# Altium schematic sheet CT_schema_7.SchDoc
size 556 x 419 mm
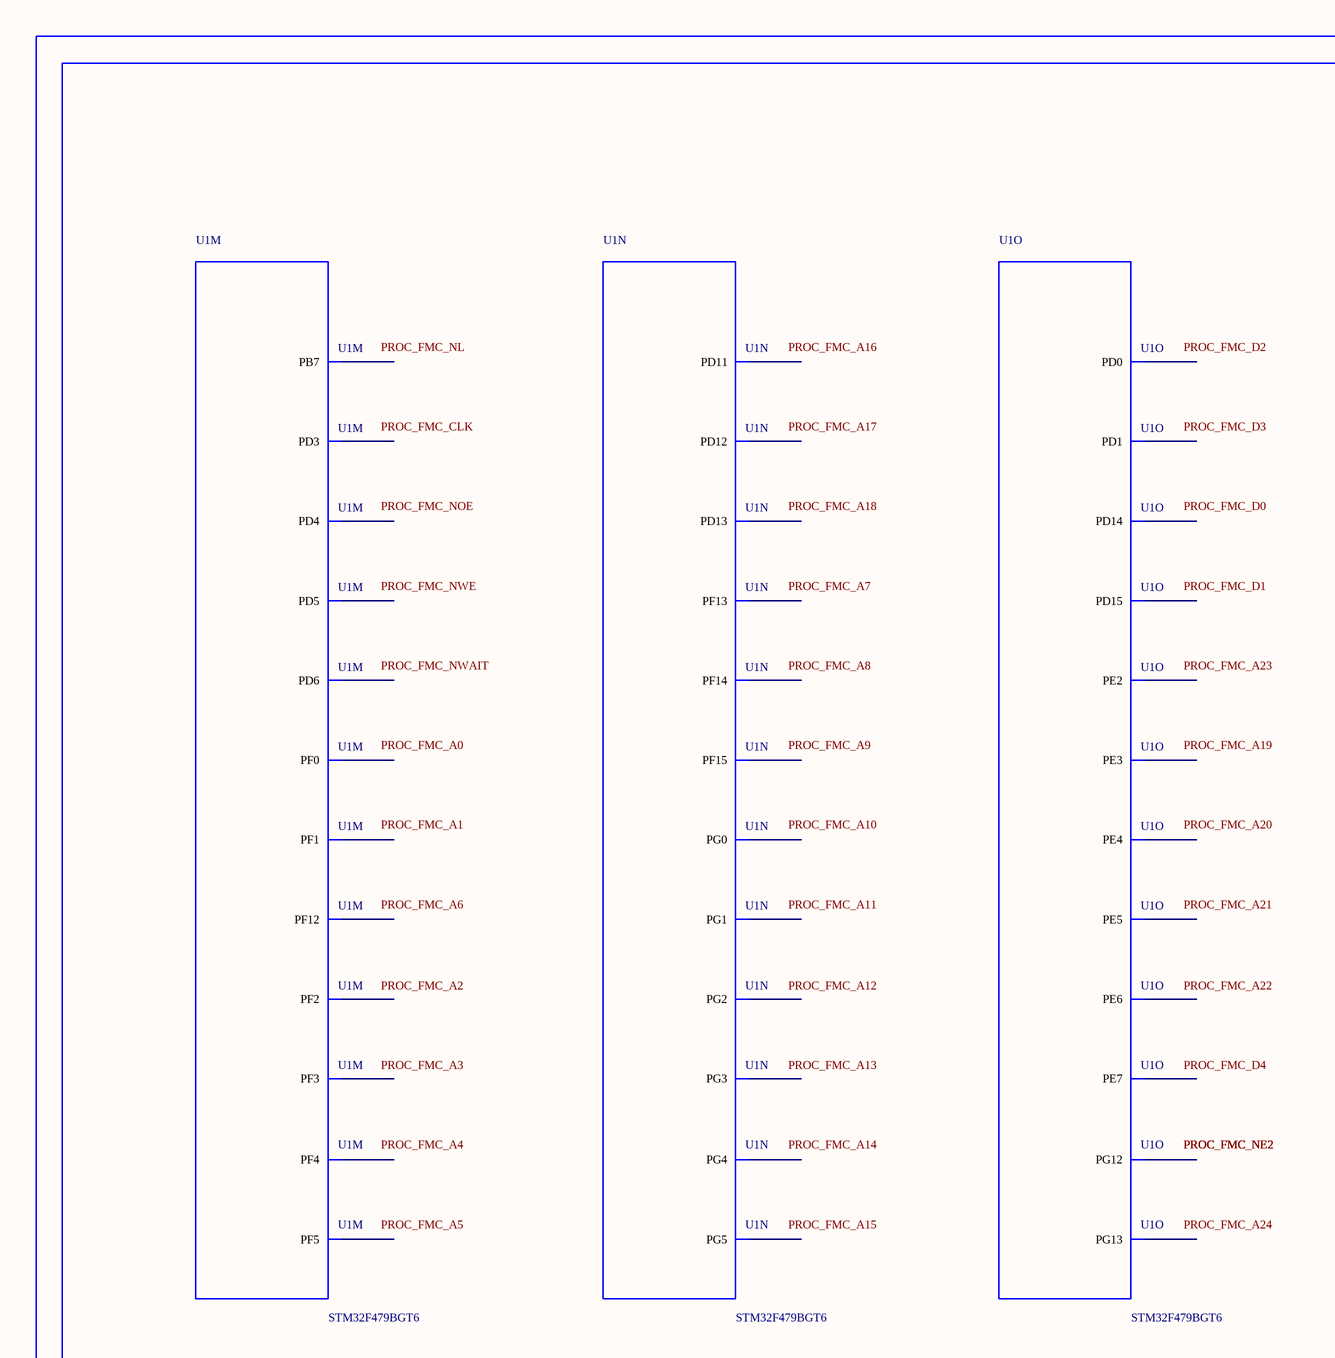
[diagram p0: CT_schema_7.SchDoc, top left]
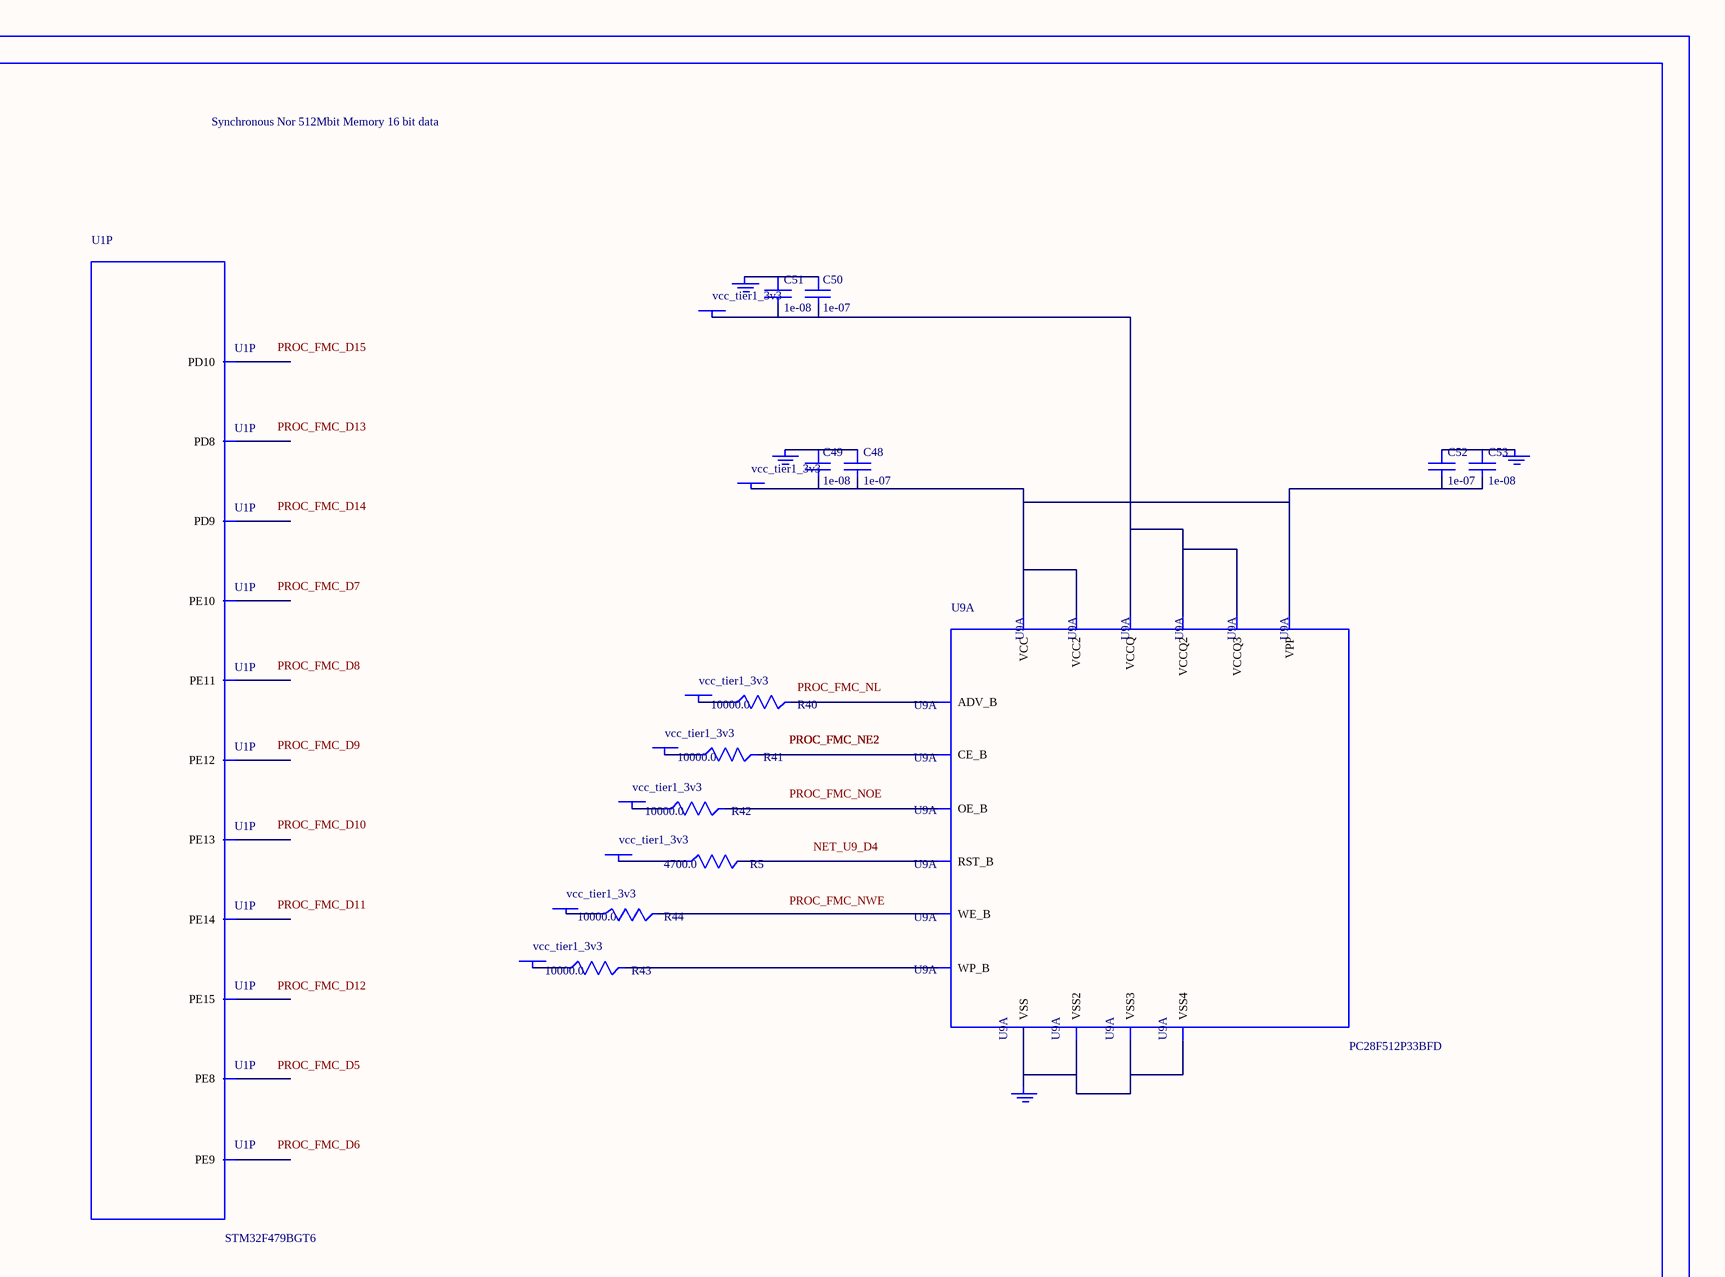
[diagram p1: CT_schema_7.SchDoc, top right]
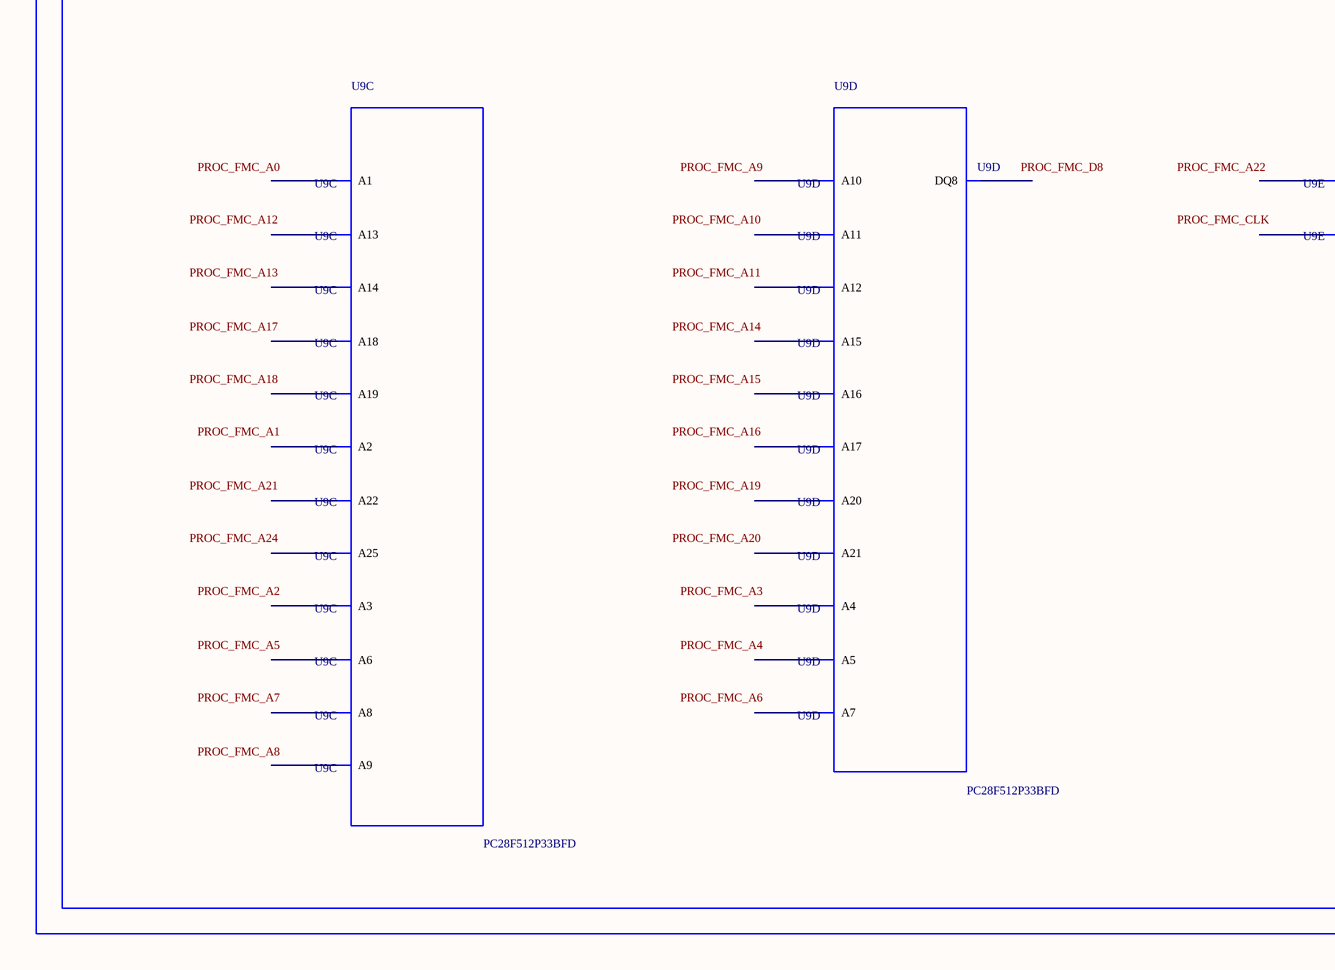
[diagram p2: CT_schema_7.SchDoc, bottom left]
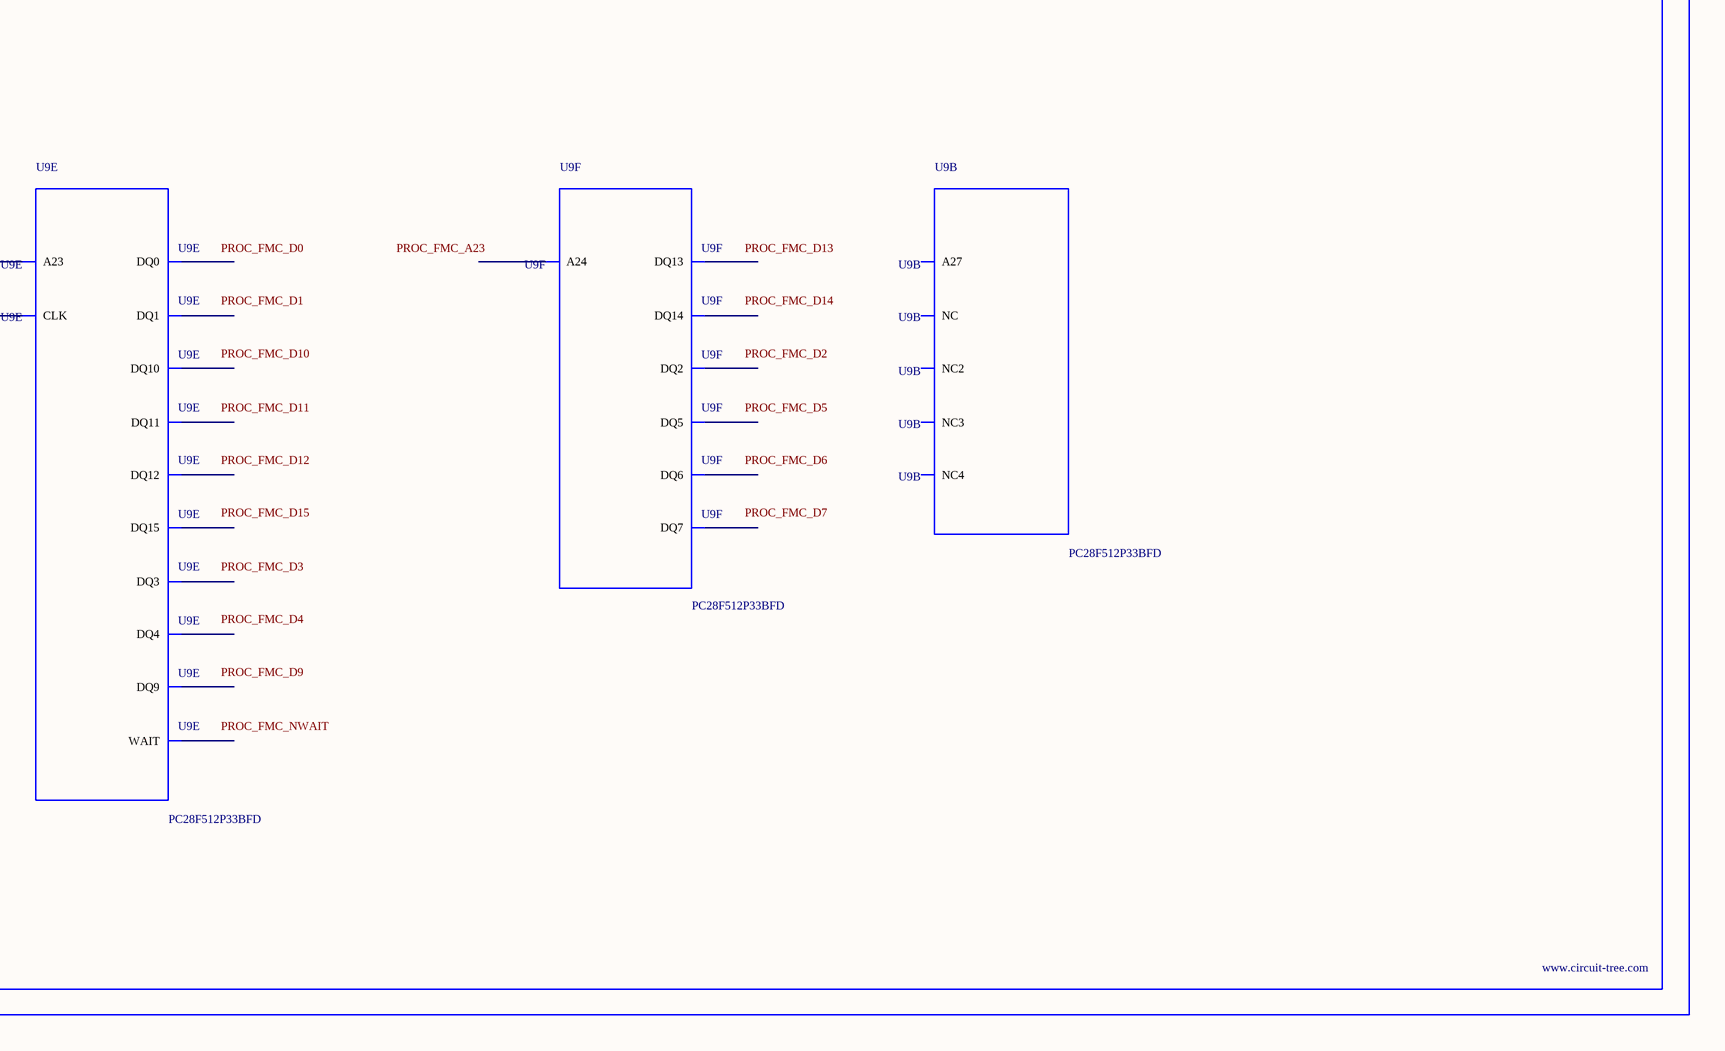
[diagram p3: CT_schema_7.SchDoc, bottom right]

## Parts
BORDER6  (no value)
C48  1e-07  [C0402]
C49  1e-08  [C0402]
C50  1e-07  [C0402]
C51  1e-08  [C0402]
C52  1e-07  [C0402]
C53  1e-08  [C0402]
GND_INSTANCE_6_0  (no value)
GND_INSTANCE_6_1  (no value)
GND_INSTANCE_6_2  (no value)
GND_INSTANCE_6_3  (no value)
POWER_INSTANCE_6_0  vcc_tier1_3v3
POWER_INSTANCE_6_1  vcc_tier1_3v3
POWER_INSTANCE_6_2  vcc_tier1_3v3
POWER_INSTANCE_6_3  vcc_tier1_3v3
POWER_INSTANCE_6_4  vcc_tier1_3v3
POWER_INSTANCE_6_5  vcc_tier1_3v3
POWER_INSTANCE_6_6  vcc_tier1_3v3
POWER_INSTANCE_6_7  vcc_tier1_3v3
R5  4700.0  [R0603]
R40  10000.0  [R0603]
R41  10000.0  [R0603]
R42  10000.0  [R0603]
R43  10000.0  [R0603]
R44  10000.0  [R0603]
U1  STM32F479BGT6  [LQFP208]  (parts M,N,O,P of 16)
U9  PC28F512P33BFD  [PC28F512P33BFD]  (parts A,B,C,D,E,F of 6)

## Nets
NetC48_1: C48.1 C49.1 GND_INSTANCE_6_0.0(GND)
NetC48_2: C48.2 C49.2 C52.2 C53.2 POWER_INSTANCE_6_0.0(PWR) U9.A4(VPP) U9.A6(VCC) U9.H3(VCC2)
NetC50_1: C50.1 C51.1 GND_INSTANCE_6_1.0(GND)
NetC50_2: C50.2 C51.2 POWER_INSTANCE_6_1.0(PWR) U9.D5(VCCQ) U9.D6(VCCQ2) U9.G4(VCCQ3)
NetC52_1: C52.1 C53.1 GND_INSTANCE_6_2.0(GND)
NetGND_INSTANCE_6_3_0: GND_INSTANCE_6_3.0(GND) U9.B2(VSS) U9.H2(VSS2) U9.H4(VSS3) U9.H6(VSS4)
NetPOWER_INSTANCE_6_2_0: POWER_INSTANCE_6_2.0(PWR) R40.1
NetPOWER_INSTANCE_6_3_0: POWER_INSTANCE_6_3.0(PWR) R41.1
NetPOWER_INSTANCE_6_4_0: POWER_INSTANCE_6_4.0(PWR) R42.1
NetPOWER_INSTANCE_6_5_0: POWER_INSTANCE_6_5.0(PWR) R43.1
NetPOWER_INSTANCE_6_6_0: POWER_INSTANCE_6_6.0(PWR) R44.1
NetPOWER_INSTANCE_6_7_0: POWER_INSTANCE_6_7.0(PWR) R5.1
NetR5_2: R5.2 U9.D4(RST_B)
NetR40_2: R40.2 U9.F6(ADV_B)
NetR41_2: R41.2 U9.B4(CE_B)
NetR42_2: R42.2 U9.F8(OE_B)
NetR43_2: R43.2 U9.C6(WP_B)
NetR44_2: R44.2 U9.G8(WE_B)

Not connected (* = marked no-connect by the designer): U1 1(PE2) 2(PE3) 3(PE4) 4(PE5) 5(PE6) 16(PF0) 17(PF1) 18(PF2) 22(PF3) 23(PF4) 24(PF5) 71(PF12) 74(PF13) 75(PF14) 76(PF15) 77(PG0) 78(PG1) 79(PE7) 80(PE8) 81(PE9) 84(PE10) 85(PE11) 86(PE12) 87(PE13) 88(PE14) 89(PE15) 108(PD8) 109(PD9) 110(PD10) 111(PD11) 112(PD12) 113(PD13) 116(PD14) 117(PD15) 129(PG2) 130(PG3) 131(PG4) 132(PG5) 164(PD0) 165(PD1) 167(PD3) 168(PD4) 169(PD5) 172(PD6) 181(PG12) 182(PG13) 196(PB7); U9 A1 A2(A6) A3(A8) A5(A13) A7(A18) A8(A22) B1(A2) B3(A9) B5(A14) B6(A25) B7(A19) B8(NC) C1(A3) C2(A7) C3(A10) C4(A12) C5(A15) C7(A20) C8(A21) D1(A4) D2(A5) D3(A11) D7(A16) D8(A17) E1(DQ8) E2(DQ1) E3(DQ9) E4(DQ3) E5(DQ4) E6(CLK) E7(DQ15) E8(NC2) F1(NC3) F2(DQ0) F3(DQ10) F4(DQ11) F5(DQ12) F7(WAIT) G1(A23) G2(NC4) G3(DQ2) G5(DQ5) G6(DQ6) G7(DQ14) H1(A27) H5(DQ13) H7(DQ7) H8(A24)

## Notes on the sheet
- Labels drawn without touching a wire or pin: NET_U9_D4, PROC_FMC_A0, PROC_FMC_A1, PROC_FMC_A2, PROC_FMC_A3, PROC_FMC_A4, PROC_FMC_A5, PROC_FMC_A6, PROC_FMC_A7, PROC_FMC_A8, PROC_FMC_A9, PROC_FMC_A10, PROC_FMC_A11, PROC_FMC_A12, PROC_FMC_A13, PROC_FMC_A14, PROC_FMC_A15, PROC_FMC_A16, PROC_FMC_A17, PROC_FMC_A18, PROC_FMC_A19, PROC_FMC_A20, PROC_FMC_A21, PROC_FMC_A22, PROC_FMC_A23, PROC_FMC_A24, PROC_FMC_CLK, PROC_FMC_D0, PROC_FMC_D1, PROC_FMC_D2, PROC_FMC_D3, PROC_FMC_D4, PROC_FMC_D5, PROC_FMC_D6, PROC_FMC_D7, PROC_FMC_D8, PROC_FMC_D9, PROC_FMC_D10, PROC_FMC_D11, PROC_FMC_D12, PROC_FMC_D13, PROC_FMC_D14, PROC_FMC_D15, PROC_FMC_NL, PROC_FMC_NOE, PROC_FMC_NWAIT, PROC_FMC_NWE

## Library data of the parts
BORDER6 = BORDER_PAGE6
C48 C50 C52 = C0402C104K3RACTU
C49 C51 C53 = C0402C103K3RAC
GND_INSTANCE_6_0-GND_INSTANCE_6_3 = GND
POWER_INSTANCE_6_0-POWER_INSTANCE_6_7 = PWR
R5 = RC0603JR-074K7L
R40-R44 = RC0603JR-0710KL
